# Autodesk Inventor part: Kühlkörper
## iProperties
Created: 2003-12
Part Number: Kühlkörper
Material: Aluminium - 6061
Document SubType Name: Modellieren
Designer: Ulrich
Control State: 0
Master: False
Checked Out: False
Shininess: 20.0
Angle Display Precision: 2
Document Length Units: 11269
Document Angle Units: 11279
Document Time Units: 11290
Document Mass Units: 11283
Document Length Units Precision: 3
Document Angle Units Precision: 2
Density: 0.0
Volumn: 0.0
Area: 0.0
PropertySet Name: Model Information
Author: Ulrich
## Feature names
1. Drehung1 [Revolution]
2. Befestigungsgewinde [Hole]
3. Gewinde_Erhitzerkopf [Hole]
4. Zylinderbohrung [Hole]
